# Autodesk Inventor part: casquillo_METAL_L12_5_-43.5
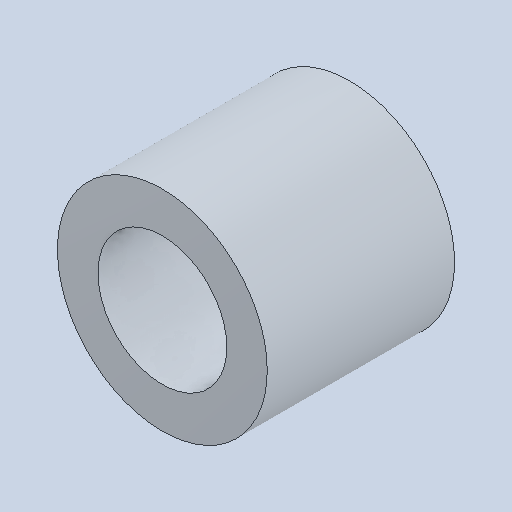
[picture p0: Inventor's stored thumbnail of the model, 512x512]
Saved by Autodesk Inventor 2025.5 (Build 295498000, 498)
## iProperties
Created: 2026-10
Part Number: casquillo_METAL_L12_5_-43.5
Material: Genérico
Document SubType Name: Modeling
Designer: Luis M
Density: 1 g/cm^3
Appearance: Valor por defecto
Author: Luis M
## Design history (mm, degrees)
feature "Base1"
node "Sólido1"
